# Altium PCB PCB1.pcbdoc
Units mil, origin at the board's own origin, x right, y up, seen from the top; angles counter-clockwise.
Board outline 2670 x 5125 mil, 2 copper layers (Top Layer, Bottom Layer), stack 62.2 mil thick; 12 components, 7 nets, 36 pads, 15 vias.
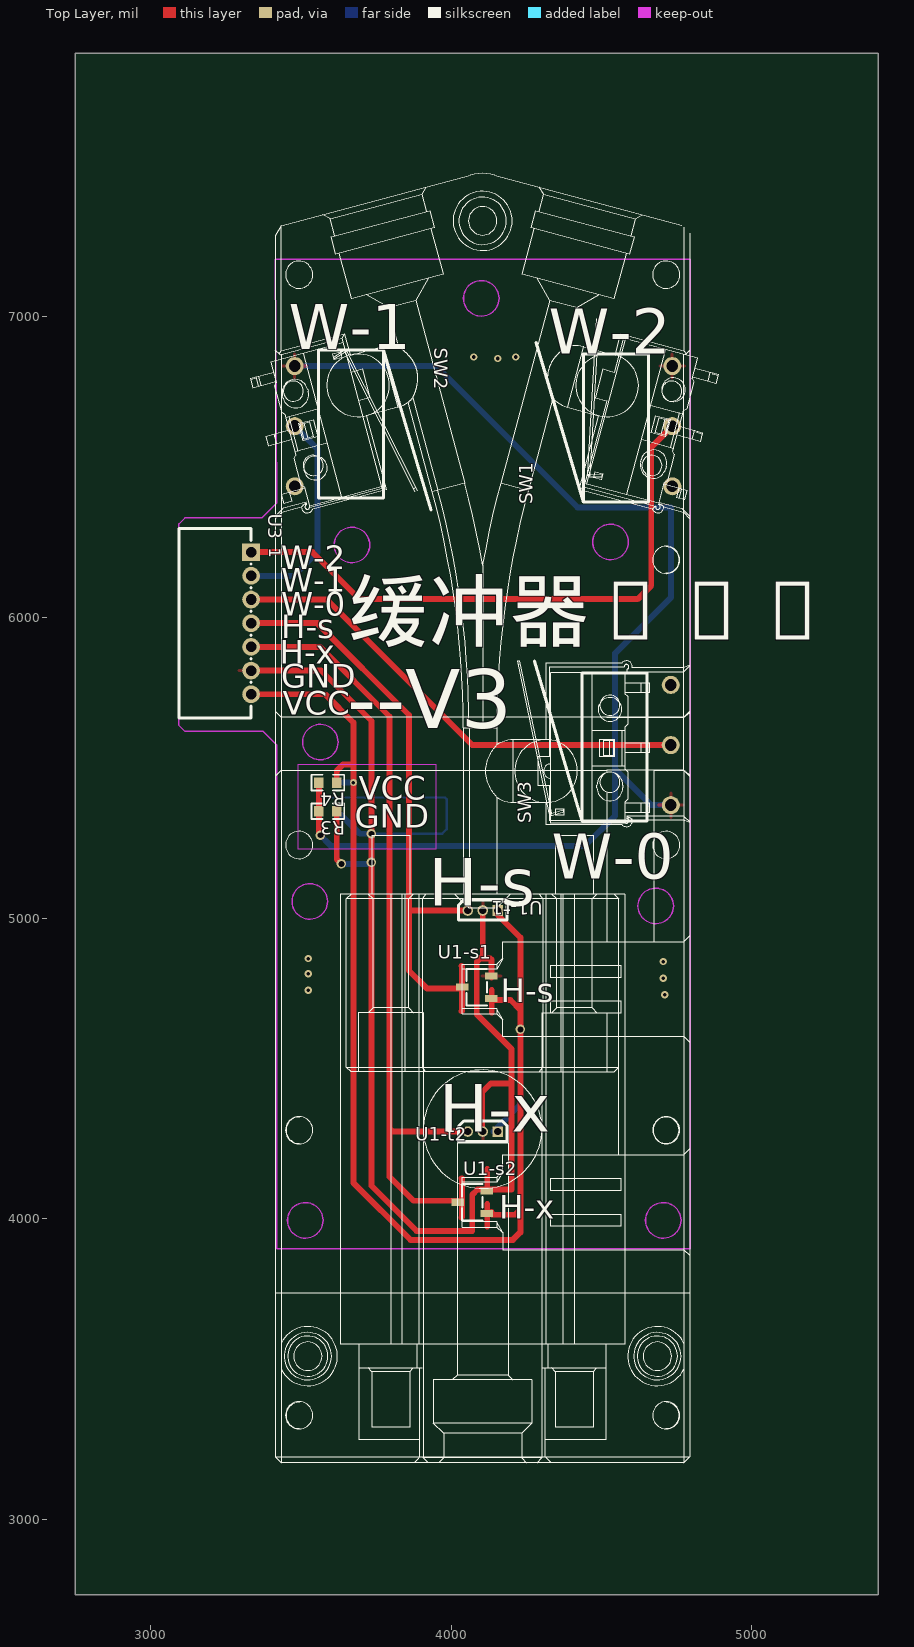
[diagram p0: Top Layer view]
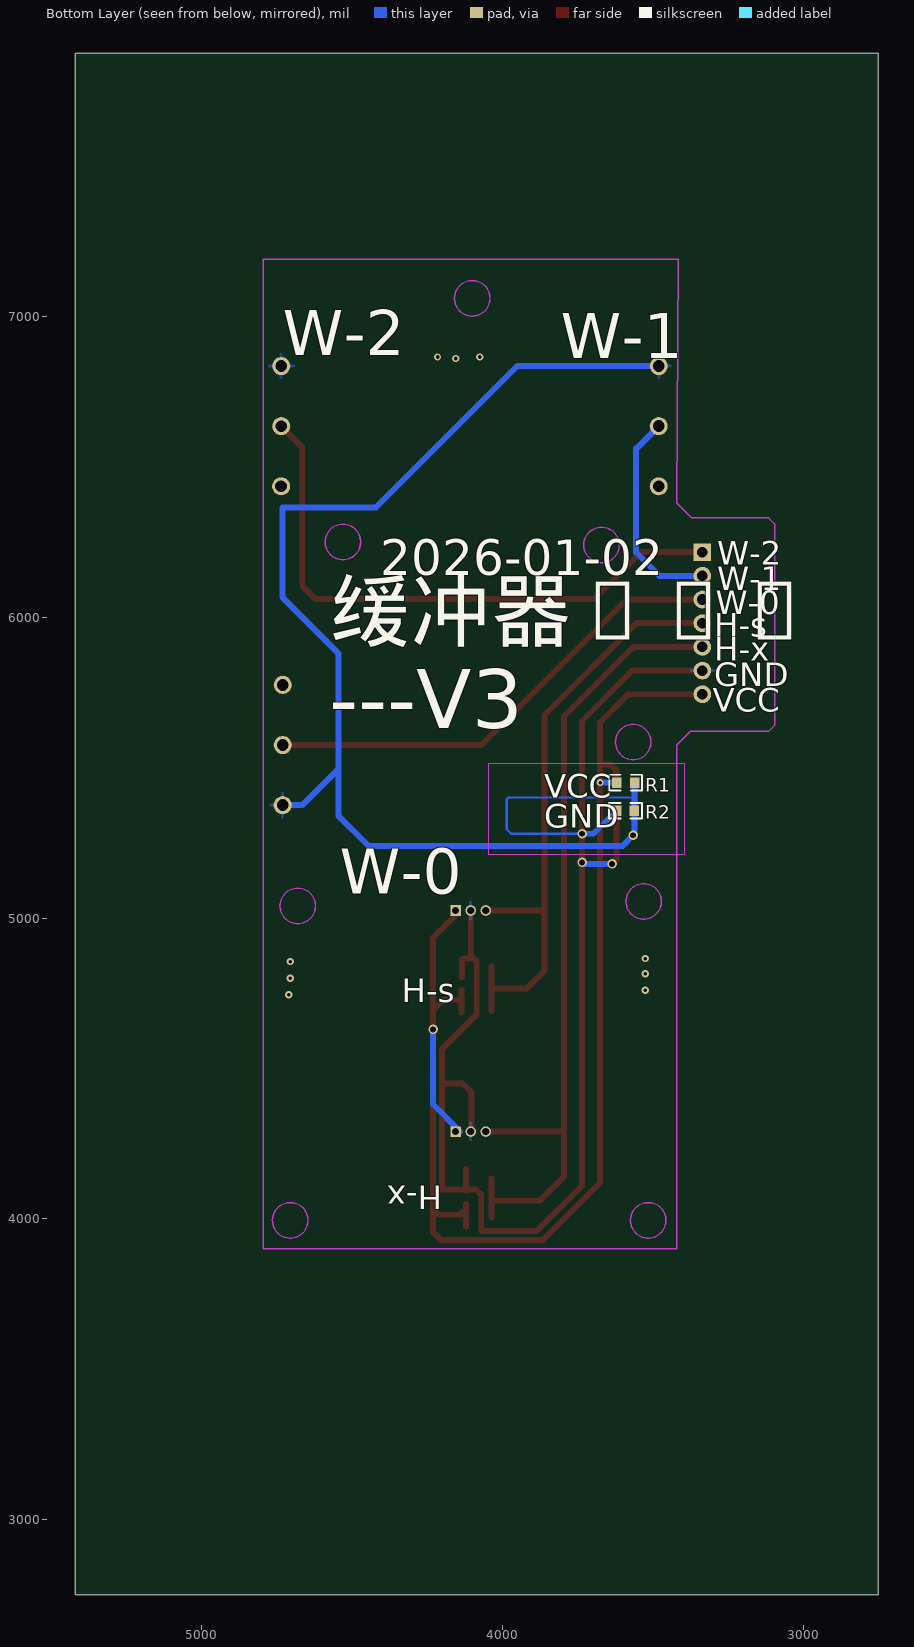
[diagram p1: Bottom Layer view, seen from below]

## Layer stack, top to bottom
Top Solder Mask Layer: solder mask 0.4, Dk 3.3
Top Layer: signal copper 1.4
Dielectric1: surface 59.4, FR4, Dk 4.5
Bottom Layer: signal copper 1.4
Bottom Solder Mask Layer: solder mask 0.4, Dk 3.3

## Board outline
5420,2750 2750,2750 2750,7875 5420,7875

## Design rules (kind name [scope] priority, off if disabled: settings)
BoardOutlineClearance copperThickness1oz [All] p0: genericclearance=10 ignorepadtopadclearanceinfootprint=FALSE except(0: Arc-SplitContinuation Track-SplitContinuation SMDPad-SplitContinuation THPad-SplitContinuation Via-SplitContinuation Fill-SplitContinuation Poly-SplitContinuation Region-SplitContinuation Text-SplitContinuation)
BoardOutlineClearance copperThickness2oz [All] p0: genericclearance=10 ignorepadtopadclearanceinfootprint=FALSE except(0: Arc-SplitContinuation Track-SplitContinuation SMDPad-SplitContinuation THPad-SplitContinuation Via-SplitContinuation Fill-SplitContinuation Poly-SplitContinuation Region-SplitContinuation Text-SplitContinuation)
BoardOutlineClearance Plane_innerPlane [All] p0: genericclearance=10 ignorepadtopadclearanceinfootprint=FALSE except(0: Arc-SplitContinuation Track-SplitContinuation SMDPad-SplitContinuation THPad-SplitContinuation Via-SplitContinuation Fill-SplitContinuation Poly-SplitContinuation Region-SplitContinuation Text-SplitContinuation)
BoardOutlineClearance Copper_copperRegion [All] p0: genericclearance=10 ignorepadtopadclearanceinfootprint=FALSE except(0: Arc-SplitContinuation Track-SplitContinuation SMDPad-SplitContinuation THPad-SplitContinuation Via-SplitContinuation Fill-SplitContinuation Poly-SplitContinuation Region-SplitContinuation Text-SplitContinuation)
BoardOutlineClearance otherClearance [All] p0: genericclearance=10 ignorepadtopadclearanceinfootprint=FALSE except(0: Arc-SplitContinuation Track-SplitContinuation SMDPad-SplitContinuation THPad-SplitContinuation Via-SplitContinuation Fill-SplitContinuation Poly-SplitContinuation Region-SplitContinuation Text-SplitContinuation)
Clearance copperThickness1oz [All] p1: gap=7 ignorepadtopadclearanceinfootprint=FALSE
Clearance copperThickness2oz [All] p1: gap=7 ignorepadtopadclearanceinfootprint=FALSE
Clearance Plane_innerPlane [All] p1: gap=7 ignorepadtopadclearanceinfootprint=FALSE
Clearance Copper_copperRegion [All] p1: gap=7 ignorepadtopadclearanceinfootprint=FALSE
Clearance otherClearance [All] p1: gap=7 ignorepadtopadclearanceinfootprint=FALSE
DiffPairsRouting differentialPair [All] p1: maxuncoupledlength=10 minlimit=6 maxlimit=Infinity mostfreqgap=6 toplayer_minwidth=5 toplayer_prefwidth=10 toplayer_maxwidth=100 bottomlayer_minwidth=5 bottomlayer_prefwidth=10 bottomlayer_maxwidth=100
PasteMaskExpansion pasteMaskExpansion [All] p1: expansion=0
PlaneConnect innerPlane [All] p1: planeconnectstyle=Relief reliefexpansion=20 reliefentries=4 reliefconductorwidth=10 reliefairgap=10
PolygonConnect copperRegion [All] p1: connectstyle=Relief reliefentries=4 reliefconductorwidth=10 polygonreliefangle="90 Angle" airgapwidth=10
RoutingVias viaSize [All] p1: viastyle="Through Hole" holewidth=12.0078 minholewidth=11.811 maxholewidth=248.0314 width=12.0078 minwidth=11.811 maxwidth=248.0314
SolderMaskExpansion solderMaskExpansion [IsVia] p1: useseparateexpansions=TRUE expansion=-1000 expansionbottom=-1000
SolderMaskExpansion solderMaskExpansion [All] p2: useseparateexpansions=TRUE expansion=2 expansionbottom=2
Width copperThickness1oz [All] p1: maxlimit=100 minlimit=5 preferedwidth=10
Width copperThickness2oz [All] p1: maxlimit=100 minlimit=8 preferedwidth=10

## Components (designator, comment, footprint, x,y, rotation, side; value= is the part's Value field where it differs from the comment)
R1 "10K" R0603#1 3590,5450 r180 bottom
R2 "10K" R0603#2 3590.5,5356.4 r180 bottom
R3 "10K" R0603#1 3590,5355 r180 top
R4 "10K" R0603#1 3590,5450 r180 top
SW1 "微动带柄左孪 ROHS 100g 微动开关" KEY-TH_100GMICROSWITCH 4735,6635 r90 top
SW2 "微动带柄左孪 ROHS 100g 微动开关" KEY-TH_100GMICROSWITCH 3480,6635 r270 top
SW3 "微动带柄左孪 ROHS 100g 微动开关" KEY-TH_100GMICROSWITCH 4730,5575 r90 top
U1-s1 "CC6207MST" SOT-23-3_L2.9-W1.6-P1.90-LS2.8-BR 4085,4770 r0 top
U1-s2 "CC6207MST" SOT-23-3_L2.9-W1.6-P1.90-LS2.8-BR 4070,4055 r0 top
U1-t1 "CC6207TO" TO-92S-3_L4.1-W1.7-P1.27-L 4105,5025 r180 top
U1-t2 "CC6207TO" TO-92S-3_L4.1-W1.7-P1.27-L 4105,4290 r180 top
U3 "WAFER-PH2.0-7PWZ" CONN-TH_7P-P2.00_XUNPU_WAFER-PH2.0-7PWZ 3335,5980 r270 top

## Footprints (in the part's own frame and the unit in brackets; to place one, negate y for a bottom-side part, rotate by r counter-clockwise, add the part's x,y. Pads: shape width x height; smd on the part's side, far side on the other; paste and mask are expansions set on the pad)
CONN-TH_7P-P2.00_XUNPU_WAFER-PH2.0-7PWZ [mil]
  rect 59.1x59.1 hole 35.4 paste+0 mask+2: 1(-236.2,0)
  round 59.1 hole 35.4 paste+0 mask+2: 2(-157.5,0) 3(-78.7,0) 4(0,0) 5(78.7,0) 6(157.5,0) 7(236.2,0)
  silkscreen extent -315,-240 315,0
KEY-TH_100GMICROSWITCH [mil]
  round 60 hole 39.4: 1(-199.9,-0.1) 2(-0.1,0.1) 3(199.9,0.1)
  silkscreen extent -253,79 279,453
R0603#1 [mil]
  rect 31.8x34 smd paste-3937 mask+2: 1(-29.7,0) 2(29.7,0)
  silkscreen extent -54,-26 54,26
R0603#2 [mil]
  rect 31.8x34 smd paste-3937 mask+2: 1(-29.7,0) 2(29.6,0)
  silkscreen extent -55,-26 54,26
SOT-23-3_L2.9-W1.6-P1.90-LS2.8-BR [mil]
  rect 42.1x23.6 smd: 1(48.6,-37.4) 2(48.6,37.4) 3(-48.6,0)
  silkscreen extent -34,-60 34,60
TO-92S-3_L4.1-W1.7-P1.27-L [mil]
  rect 35.4x35.4 hole 23.6: 1(-50,0)
  round 35.4 hole 23.6: 2(0,0) 3(50,0)
  silkscreen extent -81,-35 81,32

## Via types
v1: diameter 24, hole 12, Top Layer to Bottom Layer, 10 vias
v2: diameter 31.5, hole 19.7, Top Layer to Bottom Layer, 5 vias

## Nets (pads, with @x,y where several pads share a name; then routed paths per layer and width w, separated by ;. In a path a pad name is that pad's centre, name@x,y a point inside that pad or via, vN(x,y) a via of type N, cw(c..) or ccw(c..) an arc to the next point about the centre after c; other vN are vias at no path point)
$1N979: SW1.2 U3.1 | length 1961
  Top Layer w19.7: U3.1 3538.8,6216.2 3695,6060 4620,6060 4665,6105 4665,6565 4719.9,6619.9 SW1.2@4729.9,6619.9
$1N986: SW2.2 U3.2 | length 703.2
  Bottom Layer w19.7: U3.2 3477.5,6137.5 3555,6215 3555,6560.1 SW2.2
$1N994: SW3.2 U3.3 | length 1595.3
  Top Layer w19.7: U3.3 3586.3,6058.7 4070.1,5574.9 SW3.2
GND: R1.2 R2.1 R2.2 R3.1 R3.2 R4.2 SW1.3 SW2.1 SW3.1 U1-s1.2 U1-s2.2 U1-t1.2 U1-t2.2 U3.6 | length 9438.3
  Top Layer w19.7: U3.6 3567.5,5822.5 3735,5655 v2(3735,5280) v2(3735,5185) 3735,4110 3885,3960 4070,3960 4070,4080 4087.4,4097.4 U1-s2.2@4120,4097.4 ; R4.2 R3.2 3560.3,5279.7 v2(3565,5275) ; R3.1 3619.7,5195.3 v2(3635,5180) ; U1-t2.2@4102.1,4302.1 4102.1,4420 4132.1,4450 4200,4450 ; U1-t1.2 4105,4875 4095,4865 ; U1-s2.2 4120,4093.8 U1-s2.2@4120,4097.4 ; 4120,4165 U1-s2.2@4120,4097.4 ; U1-s1.2@4133.6,4802.4 4133.6,4861.4 4130,4865 4095,4865 ; 4095,4865 4085,4855 4085,4680 4200,4565 4200,4450 ; U1-s2.2@4120,4097.4 4200,4097.4 4200,4450
  Bottom Layer w7.9: 3560,5400 3560.3,5400.3 3560.6,5400.6 3715.6,5400.6 ; 3715,5400 3715.6,5400.6 ; v2(3735,5280) 3970,5280 3985,5295 3985,5395 3979.4,5400.6 3715.6,5400.6
  Bottom Layer w19.7: SW2.1 3950.1,6834.9 4420,6365 4730.1,6365 4730.1,6065.1 4545,5880 4545,5495 ; R1.2 3560.3,5400.3 3560.3,5356.9 R2.2 3560.9,5279.1 3600,5240 4445,5240 4545,5340 4545,5495 ; R2.1 3696.6,5280 v2(3735,5280) ; v2(3635,5180) 3730,5180 v2(3735,5185) ; SW3.1 4664.9,5375.1 4545,5495
  other v1: 4710,4745 3525,4760 4705,4800 3525,4815 4705,4855 3525,4865 4155,6860 4075,6865 4215,6865
V1: U1-s2.3 U1-t2.3 U3.5 | length 2733.6
  Top Layer w19.7: U3.5 3563.7,5901.3 3795,5670 3795,4140 3875,4060 U1-s2.3@4036.4,4060 ; 3800,4295 3805,4290 U1-t2.3@4040,4290 ; 4035,4005 4036.4,4006.4 U1-s2.3@4036.4,4060 ; 4035,4135 4036.4,4133.6 U1-s2.3@4036.4,4060
V2: U1-s1.3 U1-t1.3 U3.4 | length 2028.7
  Top Layer w19.7: U3.4 3555,5980 3860,5675 3860,4825 3920,4765 U1-s1.3@4036.4,4765 ; 3865,5025 U1-t1.3@4040,5025 ; 4035,4690 4036.4,4691.4 U1-s1.3@4036.4,4765 ; 4035,4840 4036.4,4838.6 U1-s1.3@4036.4,4765
VCC: R1.1 R4.1 U1-s1.1 U1-s2.1 U1-t1.1 U1-t2.1 U3.7 | length 4553
  Top Layer w19.7: U3.7 3581.2,5743.8 3675,5650 v1(3675,5450) 3675,4120 3865,3930 4205,3930 4230,3955 v2(4230,4630) 4230,4695 ; R4.1 3619.7,5489.7 3640,5510 3670,5510 ; U1-s2.1 U1-s2.1@4120,4019 ; 4120,3975 U1-s2.1@4120,4019 ; 4120,4050 U1-s2.1@4120,4019 ; U1-s2.1@4133.6,4022.6 4133.6,4015.4 4135.5,4013.5 4213.5,4013.5 4225,4025 ; U1-s1.1@4133.6,4727.6 U1-s1.1@4135,4727.6 ; U1-s1.1 U1-s1.1@4135,4734 ; 4135,4685 U1-s1.1@4135,4727.6 ; 4135,4760 U1-s1.1@4135,4734 ; U1-t1.1 4155,5010 4230,4935 4230,4695 ; U1-s1.1@4135,4727.6 U1-s1.1@4135,4734 ; U1-s1.1@4135,4727.6 4197.4,4727.6 4230,4695
  Bottom Layer w19.7: R1.1 v1(3675,5450) ; U1-t2.1@4140,4290 4230,4380 v2(4230,4630)
pads on no net: SW1.1 SW2.3 SW3.3

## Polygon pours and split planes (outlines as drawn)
GND on Bottom Layer (solid, remove dead copper, pour order 2): 3000,7625 3000,3000 5170,3000 5170,7625
GND on Top Layer (solid, remove dead copper, pour order 0): 3110,7360 3110,3825 5080,3825 5080,7360

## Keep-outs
Top Layer:
  region: 3490,5510 3490,5230 3950,5230 3950,5510
Bottom Layer:
  region: 3395,5515 3395,5210 4045,5210 4045,5515
Board Outline Layer:
  region: 4159.1,7060 cw(c4100,7060) 4040.9,7060 cw(c4100,7060)
  circle w0.1: c4100,7060 r59.1
  region: 4159.1,7060 cw(c4100,7060) 4040.9,7060 cw(c4100,7060)
  region: 3729.1,6240 cw(c3670,6240) 3610.9,6240 cw(c3670,6240)
  circle w0.1: c3670,6240 r59.1
  region: 3729.1,6240 cw(c3670,6240) 3610.9,6240 cw(c3670,6240)
  region: 4589.1,6250 cw(c4530,6250) 4470.9,6250 cw(c4530,6250)
  circle w0.1: c4530,6250 r59.1
  region: 4589.1,6250 cw(c4530,6250) 4470.9,6250 cw(c4530,6250)
  region: 3624.1,5585 cw(c3565,5585) 3505.9,5585 cw(c3565,5585)
  circle w0.1: c3565,5585 r59.1
  region: 3624.1,5585 cw(c3565,5585) 3505.9,5585 cw(c3565,5585)
  region: 3589.1,5055 cw(c3530,5055) 3470.9,5055 cw(c3530,5055)
  circle w0.1: c3530,5055 r59.1
  region: 3589.1,5055 cw(c3530,5055) 3470.9,5055 cw(c3530,5055)
  region: 4739.1,5040 cw(c4680,5040) 4620.9,5040 cw(c4680,5040)
  circle w0.1: c4680,5040 r59.1
  region: 4739.1,5040 cw(c4680,5040) 4620.9,5040 cw(c4680,5040)
  region: 3574.1,3995 cw(c3515,3995) 3455.9,3995 cw(c3515,3995)
  circle w0.1: c3515,3995 r59.1
  region: 3574.1,3995 cw(c3515,3995) 3455.9,3995 cw(c3515,3995)
  region: 4764.1,3995 cw(c4705,3995) 4645.9,3995 cw(c4705,3995)
  circle w0.1: c4705,3995 r59.1
  region: 4764.1,3995 cw(c4705,3995) 4645.9,3995 cw(c4705,3995)
  lines w5: 3095,5640 3115,5620 3375,5620 3420,5575 3420,3900 4795,3900 4795,7190 3415,7190 3420,6380 3370,6330 3115,6330 3095,6310 3095,5640

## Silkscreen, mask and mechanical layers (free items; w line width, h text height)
Top Silkscreen Layer:
  drawing of 890 lines, arcs and shapes, not listed
  text "W-1" at 3460,6890 h149.6
  text "W-2" at 4325,6875 h149.6
  text "W-2" at 3435,6160 h78.7
  text "W-1" at 3435,6085 h78.7
  text "W-0" at 3435,6005 h78.7
  text "H-s" at 3435,5930 h78.7
  text "H-x" at 3430,5845 h78.7
  text "GND" at 3435,5765 h78.7
  text "VCC" at 3440,5675 h78.7
  text "缓冲器PCB / --V3" at 3655,5630 h196.9
  text "VCC" at 3692.7,5393.3 h78.7
  text "GND" at 3680,5300 h78.7
  text "W-0" at 4335,5130 h149.6
  text "H-s" at 3925,5040 h157.5
  text "H-s" at 4165,4720 h78.7
  text "H-x" at 3960,4290 h157.5
  text "H-x" at 4160,4000 h78.7
Bottom Silkscreen Layer:
  text "W-2" at 4730,6870 h149.6
  text "W-1" at 3805,6860 h149.6
  text "W-2" at 3285,6175 h78.7
  text "2026-01-02" at 4405,6140 h118.1
  text "W-1" at 3286,6089.2 h78.7
  text "W-0" at 3290,6010 h78.7
  text "H-s" at 3295,5935 h78.7
  text "H-x" at 3295,5855 h78.7
  text "GND" at 3295,5770 h78.7
  text "VCC" at 3300,5685 h78.7
  text "缓冲器PCB / ---V3" at 4575,5630 h196.9
  text "VCC" at 3860,5400 h78.7
  text "GND" at 3860,5300 h78.7
  text "W-0" at 4540,5080 h149.6
  text "H-s" at 4335,4720 h78.7
  text "H-x" at 4200,4110 h78.7 r180
Top Solder Mask Layer:
  lines w19.7: 4035,4015 4035,4120 ; 4035,4710 4035,4825 ; 4120,3975 4120,4050 ; 4120,4090 4120,4160 ; 4135,4685.6 4135,4755 ; 4135,4800 4135,4850
Mechanical Layer:
  circle w0.1: c4100,7060 r59.1
  circle w0.1: c3670,6240 r59.1
  circle w0.1: c4530,6250 r59.1
  circle w0.1: c3565,5585 r59.1
  circle w0.1: c3530,5055 r59.1
  circle w0.1: c4680,5040 r59.1
  circle w0.1: c3515,3995 r59.1
  circle w0.1: c4705,3995 r59.1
